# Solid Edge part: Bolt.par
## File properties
Author: Deepak Maini
Template: Normal.par
Last saved by: Administrator
Revision: 2
Application: Solid Edge
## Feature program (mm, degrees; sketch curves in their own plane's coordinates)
sketch for "unnamed Protrusion 1" plane through (0, 0, 0) normal (0, 0, 1) x-axis (1, 0, 0)
  line (-12, 12) -> (-12, -12)
  line (-12, -12) -> (12, -12)
  line (12, -12) -> (12, 12)
  line (12, 12) -> (-12, 12)
extrude "unnamed Protrusion 1" add finite 8 along +normal
sketch for "unnamed Protrusion 2" plane through (0, 0, 0) normal (0, 0, 1) x-axis (1, 0, 0)
  circle centre (0, 0) radius 6
extrude "unnamed Protrusion 2" add finite 104 along +normal
sketch for "unnamed RevolvedCutout 1" plane through (-12, 12, 4) normal (-0.707107, -0.707107, 0) x-axis (0, 0, -1)
  arc centre (-3, 7) radius 7 from (-3, 0) to (4, 7) ccw
  line (4, 7) -> (4, 0)
  line (-3, 0) -> (4, 0)
revolve "unnamed RevolvedCutout 1" cut full turn 360 deg about sketch line (9.5376, 16.9706) -> (-8.8435, 16.9706)
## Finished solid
Body 1: solid body, 9 faces, 15 edges, 8 vertices.
  Faces by surface: plane 7, cylinder 1, torus 1
  Edges by curve: line 8, intersection 4, circle 3
Bounding box of the edges (mm; curved faces can reach further): 24.000 x 24.000 x 104.000, from (-12, -12, 0) to (12, 12, 104).
Cylindrical faces by radius (mm): R6 x1
Toroidal faces (ring radius, tube radius in mm): R9.9706 r7 x1
Planar faces by outward normal: +x 1, +y 1, +z 2, -x 1, -y 1, -z 1
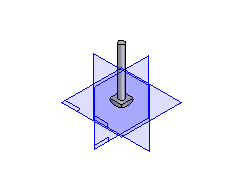
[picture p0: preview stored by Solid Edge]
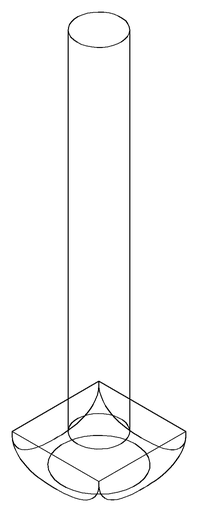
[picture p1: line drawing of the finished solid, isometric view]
